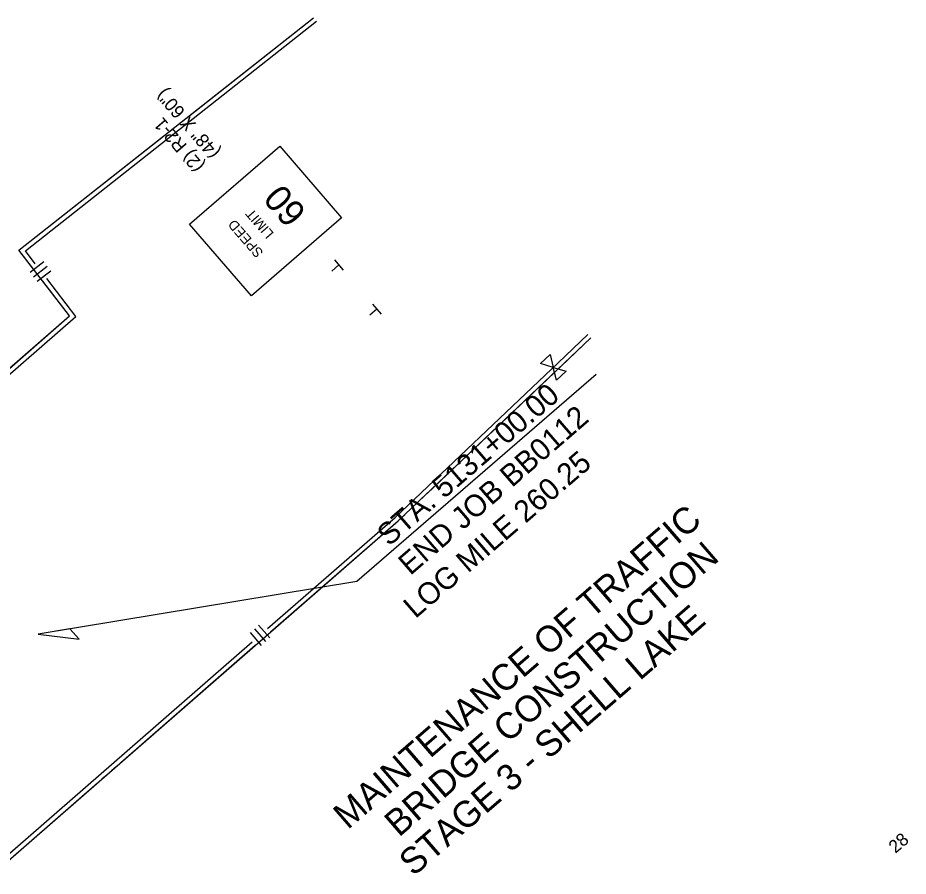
# Model space of a CAD drawing. Extents: x 259983 to 267998, y 211467 to 219827.
# Drawn here: x 265890 to 266707, y 214746 to 215534 of the extents above; entities that cross this region are included whole.
import ezdxf

# ---------------------------------------------------------------- set-up
doc = ezdxf.new("R2010")
doc.units = 0
for name, color, linetype in [('Level 24', 7, 'Continuous'), ('Level 59', 7, 'Continuous'), ('Level 6', 7, 'Continuous'), ('R-W - CofA', 7, 'Continuous'), ('R_Border Notes', 7, 'Continuous'), ('R_MOT', 7, 'Continuous')]:
    doc.layers.add(name, color=color, linetype=linetype)

msp = doc.modelspace()

# ---------------------------------------------------------------- linework, layer by layer
at = {"layer": 'Level 24'}
for points in [[(266420.94, 215206.7), (266201.33, 215016.58)], [(266201.33, 215016.58), (265908.7, 214968.29)]]:
    msp.add_lwpolyline(points, dxfattribs=at)
at = {"layer": 'Level 59'}
msp.add_lwpolyline([(265937.72, 214973.11), (265908.7, 214968.29), (265946.28, 214963.79)], close=True, dxfattribs=at)
at = {"layer": 'R-W - CofA'}
for p, q in [((265901.38, 215300.57), (265913.91, 215310.24)), ((265904.6, 215296.39), (265917.13, 215306.07)), ((265907.83, 215292.22), (265920.36, 215301.9)), ((266369.75, 215216.61), (266378.6, 215225.02)), ((266378.6, 215225.02), (266381.45, 215213.16)), ((266381.45, 215213.16), (266369.75, 215216.61)), ((266384.3, 215201.3), (266381.45, 215213.16)), ((266381.45, 215213.16), (266393.14, 215209.7)), ((266393.14, 215209.7), (266384.3, 215201.3)), ((266107.19, 214973.13), (266117.4, 214961.42)), ((266111.09, 214976.53), (266121.3, 214964.82)), ((266103.29, 214969.73), (266113.49, 214958.01))]:
    msp.add_line(p, q, dxfattribs=at)
for points in [[(265362.87, 214926.38), (265675.98, 215032.57), (265937.67, 215260.59), (265891.14, 215320.84), (266161.51, 215534.11)], [(266046.6, 215443.47), (266161.51, 215534.11)], [(265897.03, 215320.12), (266164.28, 215530.92)], [(266037.35, 215436.17), (266042.4, 215440.16)], [(266028.09, 215428.87), (266033.14, 215432.85)], [(265891.14, 215320.84), (266023.89, 215425.55)], [(265902.77, 215305.78), (265891.14, 215320.84)], [(265906.1, 215308.38), (265897.03, 215320.12)], [(265712.27, 215058.59), (265943.44, 215260.02), (265916.62, 215294.76)], [(265856.95, 215190.25), (265937.67, 215260.59), (265913.15, 215292.34)], [(265622.7, 214398.79), (265711.38, 214612.45), (266239.14, 215072.3), (266415.95, 215240.21)], [(266385.87, 215217.36), (266413.23, 215243.35)], [(266388.72, 215214.36), (266415.95, 215240.21)], [(266119.32, 214973.39), (266236.35, 215075.37), (266385.87, 215217.36)], [(266265.7, 215097.53), (266388.72, 215214.36)], [(266257.31, 215089.56), (266261.89, 215093.91)], [(266248.92, 215081.6), (266253.5, 215085.94)], [(266122.04, 214970.27), (266239.14, 215072.3), (266245.11, 215077.97)], [(265837.24, 214727.61), (266105.27, 214961.15)], [(265984.68, 214850.59), (266107.99, 214958.03)], [(265967.23, 214835.39), (265971.99, 214839.53)], [(265975.96, 214842.99), (265980.72, 214847.13)], [(265839.96, 214724.49), (265963.27, 214831.93)]]:
    msp.add_lwpolyline(points, dxfattribs=at)
at = {"layer": 'R_MOT'}
for p, q in [((266184.58, 215307.18), (266178.13, 215301.59)), ((266180.59, 215311.78), (266188.6, 215302.53)), ((266219.64, 215266.68), (266213.18, 215261.09)), ((266215.65, 215271.29), (266223.66, 215262.03))]:
    msp.add_line(p, q, dxfattribs=at)
msp.add_lwpolyline([(266047.59, 215344.7), (266130.43, 215416.35), (266187.27, 215350.62), (266104.44, 215278.98)], close=True, dxfattribs=at)

# ---------------------------------------------------------------- texts
at = {"layer": 'Level 24'}
for s, p in [('STA. 5131+00.00', (266230.66, 215048.26)), ('END JOB BB0112', (266250.23, 215021.56)), ('LOG MILE 260.25', (266254.92, 214981.97))]:
    msp.add_text(s, height=20, rotation=40.8833, dxfattribs=at).set_placement(p)
at = {"layer": 'Level 6'}
for s, p in [('MAINTENANCE OF TRAFFIC', (266192.87, 214788.3)), ('BRIDGE CONSTRUCTION', (266239.79, 214781.29)), ('STAGE 3 - SHELL LAKE', (266253.14, 214745.24))]:
    msp.add_text(s, height=24, rotation=40.8733, dxfattribs=at).set_placement(p)
at = {"layer": 'R_Border Notes'}
msp.add_text('28', height=11.775, rotation=40.8833, dxfattribs=at).set_placement((266695.5, 214766.57))
at = {"layer": 'R_MOT'}
for s, height, p in [('(48" X 60")', 12.1288, (266076.4, 215411.19)), ('(2) R2-1', 12.129, (266061.93, 215398.67)), ('60', 24.258, (266156.12, 215355.79)), ('LIMIT', 9.051, (266125.52, 215336.29)), ('SPEED', 9.051, (266115.92, 215318.8))]:
    msp.add_text(s, height=height, rotation=130.85552, dxfattribs=at).set_placement(p)

doc.saveas('drawing.dxf')
